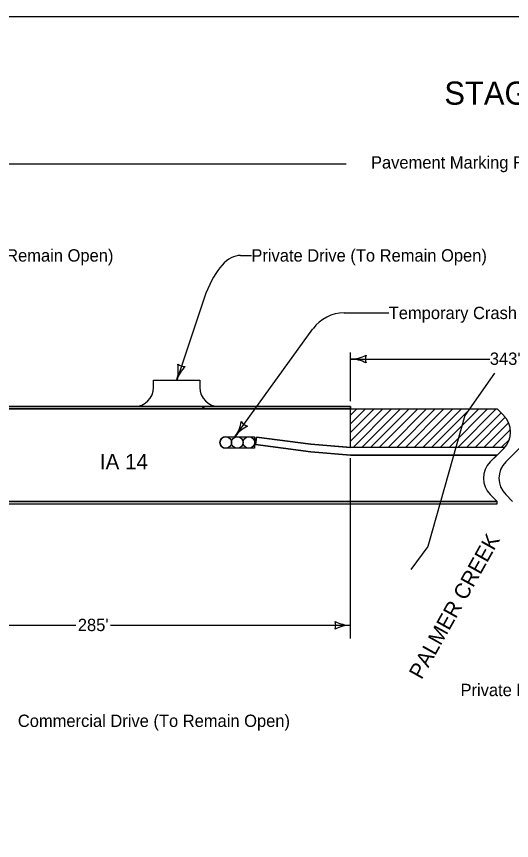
# Model space of a CAD drawing. Extents: x -2134934 to -2127057, y -2139046 to -2137036.
# Drawn here: x -2134008 to -2133366, y -2138105 to -2137036 of the extents above; entities that cross this region are included whole.
import ezdxf

# ---------------------------------------------------------------- set-up
doc = ezdxf.new("R2010")
doc.units = 0
for name, color, linetype in [('Barrier', 7, 'Continuous'), ('BridgeSuperStructureExisting', 7, 'Continuous'), ('Default', 7, 'Continuous'), ('dsnCellsNorthArrow', 7, 'Continuous'), ('DsnShtPlotIdentification', 7, 'Continuous'), ('DsnShtPlotShape', 7, 'Continuous')]:
    doc.layers.add(name, color=color, linetype=linetype)

msp = doc.modelspace()

# ---------------------------------------------------------------- linework, layer by layer
at = {"layer": 'BridgeSuperStructureExisting'}
for p, q in [((-2134239.4, -2137227), (-2133580, -2137227)), ((-2133717.4, -2137346), (-2133703.2, -2137346)), ((-2133762.1, -2137395.1), (-2133800.1, -2137507.7)), ((-2133582.7, -2137420.6), (-2133525, -2137420.6)), ((-2133724.1, -2137580.8), (-2133623.3, -2137441.3)), ((-2133574.4, -2137535.2), (-2133574.4, -2137471.9)), ((-2133574.4, -2137480.5), (-2133393.8, -2137480.5)), ((-2133574.4, -2137545.2), (-2134884.4, -2137545.2)), ((-2133745.1, -2137542.2), (-2133855.1, -2137542.2)), ((-2133574.4, -2137553.2), (-2133566.4, -2137545.2)), ((-2133574.4, -2137564.5), (-2133555.1, -2137545.2)), ((-2133574.4, -2137575.8), (-2133543.8, -2137545.2)), ((-2133574.4, -2137595.2), (-2133574.4, -2137545.2)), ((-2133574.4, -2137587.1), (-2133532.5, -2137545.2)), ((-2133574.4, -2137595.2), (-2133574.4, -2137545.2)), ((-2133571.2, -2137595.2), (-2133521.2, -2137545.2)), ((-2133559.9, -2137595.2), (-2133509.9, -2137545.2)), ((-2133548.6, -2137595.2), (-2133498.6, -2137545.2)), ((-2133537.3, -2137595.2), (-2133487.3, -2137545.2)), ((-2133525.9, -2137595.2), (-2133475.9, -2137545.2)), ((-2133514.6, -2137595.2), (-2133464.6, -2137545.2)), ((-2133453.3, -2137545.2), (-2133503.3, -2137595.2)), ((-2133492, -2137595.2), (-2133442, -2137545.2)), ((-2133480.7, -2137595.2), (-2133430.7, -2137545.2)), ((-2133469.4, -2137595.2), (-2133419.4, -2137545.2)), ((-2133458.1, -2137595.2), (-2133408.1, -2137545.2)), ((-2133446.7, -2137595.2), (-2133396.7, -2137545.2)), ((-2133435.4, -2137595.2), (-2133385.4, -2137545.2)), ((-2133375.7, -2137553.9), (-2133384.4, -2137545.2)), ((-2133424.1, -2137595.2), (-2133379.3, -2137550.3)), ((-2133412.8, -2137595.2), (-2133373.7, -2137556.1)), ((-2133401.5, -2137595.2), (-2133369.4, -2137563.1)), ((-2133390.2, -2137595.2), (-2133367, -2137572)), ((-2133736.5, -2137581.3), (-2133699, -2137581.3)), ((-2133736.5, -2137581.3), (-2133699, -2137581.3)), ((-2133699, -2137581.3), (-2133699, -2137596.3)), ((-2133699, -2137581.3), (-2133699, -2137596.3)), ((-2133696.7, -2137581.7), (-2133698, -2137591.5)), ((-2133696.7, -2137581.7), (-2133698, -2137591.5)), ((-2133698, -2137591.5), (-2133696.7, -2137581.7)), ((-2133698, -2137591.5), (-2133696.7, -2137581.7)), ((-2133626.2, -2137590.8), (-2133696.7, -2137581.7)), ((-2133626.2, -2137590.8), (-2133696.7, -2137581.7)), ((-2133626.2, -2137590.8), (-2133696.7, -2137581.7)), ((-2133696.7, -2137581.7), (-2133626.2, -2137590.8)), ((-2133378.9, -2137595.2), (-2133368.4, -2137584.7)), ((-2133699, -2137596.3), (-2133736.5, -2137596.3)), ((-2133699, -2137596.3), (-2133736.5, -2137596.3)), ((-2133698, -2137591.5), (-2133626, -2137600.8)), ((-2133626, -2137600.8), (-2133698, -2137591.5)), ((-2133626, -2137600.8), (-2133698, -2137591.5)), ((-2133697.9, -2137591.5), (-2133626, -2137600.8)), ((-2133574.1, -2137595.2), (-2133626.2, -2137590.8)), ((-2133574.4, -2137595.1), (-2133626.2, -2137590.8)), ((-2133574.4, -2137595.2), (-2133626.2, -2137590.8)), ((-2133626.2, -2137590.8), (-2133574.4, -2137595.2)), ((-2133626, -2137600.8), (-2133574.4, -2137605.2)), ((-2133626, -2137600.8), (-2133574.4, -2137605.2)), ((-2133574.4, -2137605.2), (-2133626, -2137600.8)), ((-2133574.4, -2137605.2), (-2133626, -2137600.8)), ((-2133574.4, -2137595.2), (-2133574.4, -2137595.1)), ((-2133574.2, -2137595.2), (-2133574.4, -2137595.2)), ((-2133374.5, -2137595.2), (-2133574.4, -2137595.2)), ((-2133574.1, -2137595.2), (-2133574.2, -2137595.2)), ((-2133374.5, -2137595.2), (-2133574.1, -2137595.2)), ((-2133393.2, -2137613.9), (-2133375.7, -2137596.4)), ((-2133384.4, -2137605.2), (-2133375.7, -2137596.4)), ((-2133373.2, -2137613.9), (-2133355.7, -2137596.4)), ((-2133574.4, -2137605.2), (-2133384.4, -2137605.2)), ((-2133574.4, -2137605.2), (-2133384.4, -2137605.2)), ((-2133384.4, -2137605.2), (-2133574.4, -2137605.2)), ((-2133384.4, -2137605.2), (-2133574.4, -2137605.2)), ((-2133574.4, -2137843.1), (-2133574.4, -2137609.3)), ((-2133393.2, -2137613.9), (-2133384.4, -2137605.2)), ((-2134884.4, -2137665.2), (-2133384.4, -2137665.2)), ((-2133384.4, -2137665.2), (-2133393.2, -2137656.4)), ((-2133384.4, -2137665.2), (-2133393.2, -2137656.4)), ((-2133364.4, -2137665.2), (-2133373.2, -2137656.4)), ((-2133373.2, -2137656.4), (-2133364.4, -2137665.2)), ((-2134234.4, -2137826), (-2133930.9, -2137826)), ((-2133886, -2137826), (-2133574.4, -2137826)), ((-2133851.4, -2137826), (-2133801.8, -2137826))]:
    msp.add_line(p, q, dxfattribs=at)
for points in [[(-2133387.7, -2137498.8), (-2133426.4, -2137553.8), (-2133474.3, -2137723.9), (-2133496.3, -2137753.6)], [(-2133830.1, -2137517.2), (-2133830.1, -2137507.7), (-2133770.1, -2137507.7), (-2133770.1, -2137517.2)], [(-2133574.4, -2137545.2), (-2133384.4, -2137545.2)], [(-2133736.5, -2137581.3), (-2133736.5, -2137581.3)], [(-2133736.5, -2137596.3), (-2133736.5, -2137596.3)], [(-2133574.1, -2137595.2), (-2133574.1, -2137595.2)], [(-2133384.4, -2137605.2), (-2133384.4, -2137605.2)], [(-2133384.4, -2137605.2), (-2133384.4, -2137605.2)], [(-2133364.4, -2137605.2), (-2133364.4, -2137605.2), (-2133373.2, -2137613.9)]]:
    msp.add_lwpolyline(points, dxfattribs=at)
for centre in [(-2133736.5, -2137588.8), (-2133736.5, -2137588.8), (-2133721.5, -2137588.8), (-2133721.5, -2137588.8), (-2133706.5, -2137588.8), (-2133706.5, -2137588.8)]:
    msp.add_circle(centre, 7.5, dxfattribs=at)
for centre, radius, start, end in [((-2133582.7, -2137470.6), 50, 90, 144.138), ((-2133574.4, -2137438), 42.5, 270, 298.0725), ((-2133574.4, -2137523), 42.5, 61.9275, 90), ((-2133538.8, -2137480.5), 16.4, 162.2666, 197.7334), ((-2133855.1, -2137517.2), 25, 270, 360), ((-2133745.1, -2137517.2), 25, 180, 270), ((-2133396.9, -2137575.2), 30, 315, 45), ((-2133736.5, -2137588.8), 7.5, 90.0028, 269.9972), ((-2133396.9, -2137575.2), 30, 315, 318.1884), ((-2133372, -2137635.2), 30, 135, 225), ((-2133372, -2137635.2), 30, 135, 225), ((-2133352, -2137635.2), 30, 135, 225), ((-2133352, -2137635.2), 30, 135, 225)]:
    msp.add_arc(centre, radius, start, end, dxfattribs=at)
msp.add_ellipse((-2133717.4, -2137558.9), major_axis=(0, 212.9), ratio=0.328743, start_param=0, end_param=0.693162, dxfattribs=at)
at = {"layer": 'Default'}
msp.add_lwpolyline([(-2134934.4, -2137035.9), (-2131799.4, -2137035.9), (-2131799.4, -2139045.9), (-2134934.4, -2139045.9)], close=True, dxfattribs=at)
at = {"layer": 'DsnShtPlotIdentification'}
for p, q in [((-2133766.5, -2137542.2), (-2134239.4, -2137542.2)), ((-2134239.4, -2137545.2), (-2133764.3, -2137545.2)), ((-2133574.4, -2137542.2), (-2133766.5, -2137542.2)), ((-2133766.5, -2137542.2), (-2133764.3, -2137545.2)), ((-2133764.3, -2137545.2), (-2133766.5, -2137542.2)), ((-2133574.4, -2137545.2), (-2133574.4, -2137542.2)), ((-2133574.4, -2137542.2), (-2133574.4, -2137545.2)), ((-2134884.4, -2137665.2), (-2133384.4, -2137665.2)), ((-2134884.4, -2137665.2), (-2133384.4, -2137665.2)), ((-2133384.4, -2137665.2), (-2134234.4, -2137665.2)), ((-2133384.4, -2137668.2), (-2133384.4, -2137665.2)), ((-2133384.4, -2137668.2), (-2133384.4, -2137665.2)), ((-2134884.4, -2137668.2), (-2133384.4, -2137668.2)), ((-2134884.4, -2137668.2), (-2133384.4, -2137668.2))]:
    msp.add_line(p, q, dxfattribs=at)
for points in [[(-2134884.9, -2137545.2), (-2133574.9, -2137545.2)], [(-2134884.4, -2137542.2), (-2133574.4, -2137542.2)], [(-2134884.4, -2137545.2), (-2133574.4, -2137545.2)], [(-2133764.3, -2137545.2), (-2133574.9, -2137545.2), (-2133574.4, -2137545.2)]]:
    msp.add_lwpolyline(points, dxfattribs=at)
at = {"layer": 'DsnShtPlotShape'}
for centre, radius, start, end in [((-2133840.5, -2137494.6), 42.5, 342.0849, 10.1574), ((-2133759.6, -2137520.7), 42.5, 134.0124, 162.0849), ((-2133789.1, -2137473.8), 16.4, 234.3516, 269.8183), ((-2133758.3, -2137555.6), 42.5, 323.701, 351.7735), ((-2133689.8, -2137606), 42.5, 115.6285, 143.701), ((-2133703, -2137552.1), 16.4, 215.9676, 251.4343), ((-2133610.1, -2137826), 16.4, 342.2666, 17.7333), ((-2133574.4, -2137783.5), 42.5, 241.9275, 270), ((-2133574.4, -2137868.5), 42.5, 90, 118.0725)]:
    msp.add_arc(centre, radius, start, end, dxfattribs=at)

# ---------------------------------------------------------------- texts
at = {"layer": 'Barrier'}
msp.add_text('STAGE 1', height=30, dxfattribs=at).set_placement((-2133452.8, -2137150.4))
at = {"layer": 'BridgeSuperStructureExisting'}
for s, p in [('Pavement Marking Removal Limits', (-2133548, -2137233.3)), ('Private Drive (To Remain Open)', (-2134187.8, -2137354)), ('Private Drive (To Remain Open)', (-2133703.2, -2137354)), ('Temporary Crash Cushion', (-2133525, -2137428.6)), ("343'", (-2133393.8, -2137488)), ("285'", (-2133928.4, -2137833.5)), ('Private Drive (To Remain Open)', (-2133431.8, -2137917.9)), ('Commercial Drive (To Remain Open)', (-2134006.2, -2137957.9))]:
    msp.add_text(s, height=16, dxfattribs=at).set_placement(p)
at = {"layer": 'dsnCellsNorthArrow'}
msp.add_text('IA 14', height=20, dxfattribs=at).set_placement((-2133899.8, -2137623.6))
msp.add_text('PALMER CREEK', height=20, rotation=60.7624, dxfattribs=at).set_placement((-2133482.4, -2137897.4))

doc.saveas('drawing.dxf')
